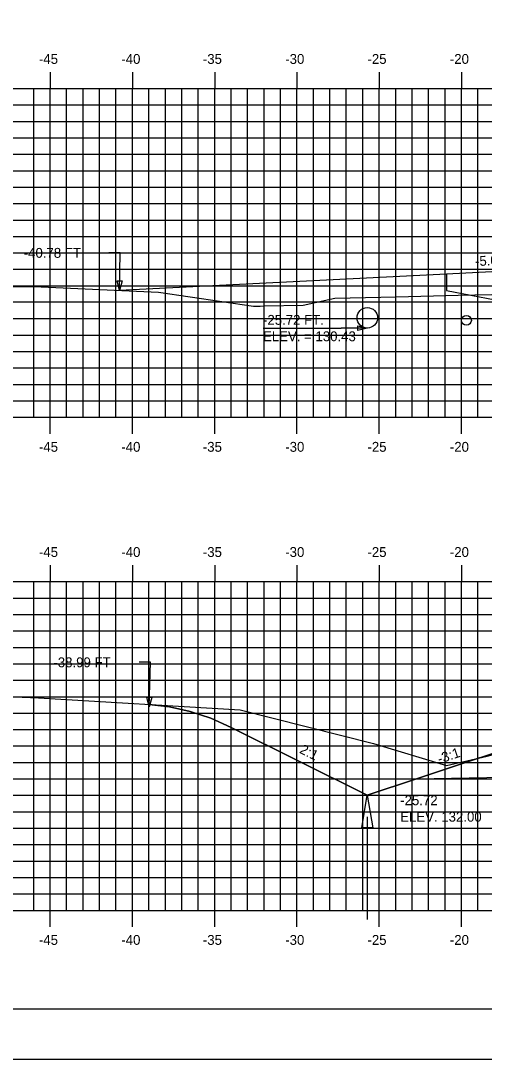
# Model space of a CAD drawing. Extents: x 1145416 to 1145586, y 608981 to 609091.
# Drawn here: x 1145452.1 to 1145480.3, y 608981.3 to 609044.5 of the extents above; entities that cross this region are included whole.
import ezdxf

# ---------------------------------------------------------------- set-up
doc = ezdxf.new("R2010")
doc.units = 0
for name, color, linetype in [('ANNOTATION', 7, 'Continuous'), ('BORDER', 7, 'Continuous'), ('D_Drainage_Culvert', 7, 'Continuous'), ('D_Drainage_Ditch_Line', 7, 'Continuous'), ('D_Roadway_SlopeLines', 7, 'Continuous'), ('D_Roadway_SubGrade', 7, 'Continuous'), ('D_Text_Standard', 7, 'Continuous'), ('H_V ANNOTATION', 7, 'Continuous'), ('MAJOR', 7, 'Continuous'), ('MINOR', 7, 'Continuous'), ('PLOT BOUNDARY', 7, 'Continuous'), ('S_Drainage_Invert', 7, 'Continuous'), ('S_Roadway_Centerline', 7, 'Continuous')]:
    doc.layers.add(name, color=color, linetype=linetype)

msp = doc.modelspace()

# ---------------------------------------------------------------- linework, layer by layer
msp.add_lwpolyline([(1145459.897, 609002.864), (1145461.147, 609002.721), (1145462.397, 609002.44), (1145463.647, 609002.022), (1145464.897, 609001.465), (1145473.164, 608997.332), (1145476.164, 608998.332), (1145483.888, 609000.906), (1145483.889, 609000.906), (1145487.889, 609001.066), (1145498.889, 609001.286), (1145509.889, 609001.066), (1145515.987, 609000.823), (1145523.577, 608998.293), (1145526.577, 608997.293), (1145535.165, 609001.587), (1145536.415, 609002.14), (1145537.665, 609002.548), (1145538.915, 609002.812), (1145540.165, 609002.931)])
at = {"layer": 'BORDER'}
msp.add_lwpolyline([(1145423.889, 608984.335), (1145583.889, 608984.335), (1145583.889, 609089.335), (1145423.889, 609089.335)], close=True, dxfattribs=at)
at = {"layer": 'D_Drainage_Culvert'}
msp.add_circle((1145473.164, 609026.386), 0.625, dxfattribs=at)
at = {"layer": 'D_Drainage_Ditch_Line'}
msp.add_line((1145473.164, 608996.02), (1145473.164, 608989.776), dxfattribs=at)
msp.add_lwpolyline([(1145473.492, 608995.363), (1145472.836, 608995.363), (1145473.164, 608997.332)], close=True, dxfattribs=at)
at = {"layer": 'D_Roadway_SlopeLines'}
msp.add_line((1145477.987, 609029.04), (1145458.109, 609028.05), dxfattribs=at)
for points in [[(1145473.164, 608997.332), (1145464.897, 609001.465), (1145463.647, 609002.022), (1145462.397, 609002.44), (1145461.147, 609002.721), (1145459.897, 609002.864)], [(1145476.164, 608998.332), (1145473.164, 608997.332)]]:
    msp.add_lwpolyline(points, dxfattribs=at)
at = {"layer": 'D_Roadway_SubGrade'}
for points in [[(1145477.987, 609028.04), (1145483.889, 609026.915), (1145487.889, 609026.995), (1145487.889, 609029.079), (1145487.889, 609029.245), (1145483.889, 609029.085), (1145483.889, 609029.335), (1145477.987, 609029.04)], [(1145487.889, 609000.65), (1145487.889, 609000.816), (1145483.889, 609000.656), (1145483.889, 609000.906), (1145483.888, 609000.906), (1145476.164, 608998.332), (1145487.889, 608998.566)]]:
    msp.add_lwpolyline(points, close=True, dxfattribs=at)
at = {"layer": 'D_Text_Standard'}
msp.add_line((1145466.825, 609025.761), (1145471.583, 609025.761), dxfattribs=at)
for points in [[(1145458.109, 609028.05), (1145458.139, 609030.337), (1145457.459, 609030.337)], [(1145473.164, 609025.761), (1145472.263, 609025.761), (1145471.583, 609025.761)], [(1145459.897, 609002.715), (1145459.986, 609005.425), (1145459.306, 609005.425)]]:
    msp.add_lwpolyline(points, dxfattribs=at)
for points in [[(1145458.109, 609028.05), (1145457.971, 609028.634), (1145458.262, 609028.63)], [(1145473.164, 609025.761), (1145472.582, 609025.615), (1145472.582, 609025.906)], [(1145459.897, 609002.715), (1145459.771, 609003.302), (1145460.061, 609003.292)]]:
    msp.add_lwpolyline(points, close=True, dxfattribs=at)
at = {"layer": 'MAJOR'}
for p, q in [((1145453.889, 609041.337), (1145453.889, 609040.335)), ((1145458.889, 609041.337), (1145458.889, 609040.335)), ((1145463.889, 609041.337), (1145463.889, 609040.335)), ((1145468.889, 609041.337), (1145468.889, 609040.335)), ((1145473.889, 609041.337), (1145473.889, 609040.335)), ((1145478.889, 609041.337), (1145478.889, 609040.335)), ((1145428.889, 609040.335), (1145568.889, 609040.335)), ((1145428.889, 609040.335), (1145568.889, 609040.335)), ((1145453.889, 609020.335), (1145453.889, 609040.335)), ((1145458.889, 609020.335), (1145458.889, 609040.335)), ((1145463.889, 609020.335), (1145463.889, 609040.335)), ((1145468.889, 609020.335), (1145468.889, 609040.335)), ((1145473.889, 609020.335), (1145473.889, 609040.335)), ((1145478.889, 609020.335), (1145478.889, 609040.335)), ((1145428.889, 609035.335), (1145568.889, 609035.335)), ((1145428.889, 609030.335), (1145568.889, 609030.335)), ((1145428.889, 609025.335), (1145568.889, 609025.335)), ((1145428.889, 609020.335), (1145568.889, 609020.335)), ((1145428.889, 609020.335), (1145568.889, 609020.335)), ((1145453.889, 609019.333), (1145453.889, 609020.335)), ((1145458.889, 609019.333), (1145458.889, 609020.335)), ((1145463.889, 609019.333), (1145463.889, 609020.335)), ((1145468.889, 609019.333), (1145468.889, 609020.335)), ((1145473.889, 609019.333), (1145473.889, 609020.335)), ((1145478.889, 609019.333), (1145478.889, 609020.335)), ((1145453.889, 609011.337), (1145453.889, 609010.335)), ((1145458.889, 609011.337), (1145458.889, 609010.335)), ((1145463.889, 609011.337), (1145463.889, 609010.335)), ((1145468.889, 609011.337), (1145468.889, 609010.335)), ((1145473.889, 609011.337), (1145473.889, 609010.335)), ((1145478.889, 609011.337), (1145478.889, 609010.335)), ((1145428.889, 609010.335), (1145568.889, 609010.335)), ((1145428.889, 609010.335), (1145568.889, 609010.335)), ((1145453.889, 608990.335), (1145453.889, 609010.335)), ((1145458.889, 608990.335), (1145458.889, 609010.335)), ((1145463.889, 608990.335), (1145463.889, 609010.335)), ((1145468.889, 608990.335), (1145468.889, 609010.335)), ((1145473.889, 608990.335), (1145473.889, 609010.335)), ((1145478.889, 608990.335), (1145478.889, 609010.335)), ((1145428.889, 609005.335), (1145568.889, 609005.335)), ((1145428.889, 609000.335), (1145568.889, 609000.335)), ((1145428.889, 608995.335), (1145568.889, 608995.335)), ((1145428.889, 608990.335), (1145568.889, 608990.335)), ((1145428.889, 608990.335), (1145568.889, 608990.335)), ((1145453.889, 608989.333), (1145453.889, 608990.335)), ((1145458.889, 608989.333), (1145458.889, 608990.335)), ((1145463.889, 608989.333), (1145463.889, 608990.335)), ((1145468.889, 608989.333), (1145468.889, 608990.335)), ((1145473.889, 608989.333), (1145473.889, 608990.335)), ((1145478.889, 608989.333), (1145478.889, 608990.335))]:
    msp.add_line(p, q, dxfattribs=at)
at = {"layer": 'MINOR'}
for p, q in [((1145452.889, 609020.335), (1145452.889, 609040.335)), ((1145454.889, 609020.335), (1145454.889, 609040.335)), ((1145455.889, 609020.335), (1145455.889, 609040.335)), ((1145456.889, 609020.335), (1145456.889, 609040.335)), ((1145457.889, 609020.335), (1145457.889, 609040.335)), ((1145459.889, 609020.335), (1145459.889, 609040.335)), ((1145460.889, 609020.335), (1145460.889, 609040.335)), ((1145461.889, 609020.335), (1145461.889, 609040.335)), ((1145462.889, 609020.335), (1145462.889, 609040.335)), ((1145464.889, 609020.335), (1145464.889, 609040.335)), ((1145465.889, 609020.335), (1145465.889, 609040.335)), ((1145466.889, 609020.335), (1145466.889, 609040.335)), ((1145467.889, 609020.335), (1145467.889, 609040.335)), ((1145469.889, 609020.335), (1145469.889, 609040.335)), ((1145470.889, 609020.335), (1145470.889, 609040.335)), ((1145471.889, 609020.335), (1145471.889, 609040.335)), ((1145472.889, 609020.335), (1145472.889, 609040.335)), ((1145474.889, 609020.335), (1145474.889, 609040.335)), ((1145475.889, 609020.335), (1145475.889, 609040.335)), ((1145476.889, 609020.335), (1145476.889, 609040.335)), ((1145477.889, 609020.335), (1145477.889, 609040.335)), ((1145479.889, 609020.335), (1145479.889, 609040.335)), ((1145428.889, 609039.335), (1145568.889, 609039.335)), ((1145428.889, 609038.335), (1145568.889, 609038.335)), ((1145428.889, 609037.335), (1145568.889, 609037.335)), ((1145428.889, 609036.335), (1145568.889, 609036.335)), ((1145428.889, 609034.335), (1145568.889, 609034.335)), ((1145428.889, 609033.335), (1145568.889, 609033.335)), ((1145428.889, 609032.335), (1145568.889, 609032.335)), ((1145428.889, 609031.335), (1145568.889, 609031.335)), ((1145428.889, 609029.335), (1145568.889, 609029.335)), ((1145428.889, 609028.335), (1145568.889, 609028.335)), ((1145568.889, 609027.335), (1145428.889, 609027.335)), ((1145428.889, 609026.335), (1145568.889, 609026.335)), ((1145428.889, 609024.335), (1145568.889, 609024.335)), ((1145428.889, 609023.335), (1145568.889, 609023.335)), ((1145428.889, 609022.335), (1145568.889, 609022.335)), ((1145428.889, 609021.335), (1145568.889, 609021.335)), ((1145452.889, 608990.335), (1145452.889, 609010.335)), ((1145454.889, 608990.335), (1145454.889, 609010.335)), ((1145455.889, 608990.335), (1145455.889, 609010.335)), ((1145456.889, 608990.335), (1145456.889, 609010.335)), ((1145457.889, 608990.335), (1145457.889, 609010.335)), ((1145459.889, 608990.335), (1145459.889, 609010.335)), ((1145460.889, 608990.335), (1145460.889, 609010.335)), ((1145461.889, 608990.335), (1145461.889, 609010.335)), ((1145462.889, 608990.335), (1145462.889, 609010.335)), ((1145464.889, 608990.335), (1145464.889, 609010.335)), ((1145465.889, 608990.335), (1145465.889, 609010.335)), ((1145466.889, 608990.335), (1145466.889, 609010.335)), ((1145467.889, 608990.335), (1145467.889, 609010.335)), ((1145469.889, 608990.335), (1145469.889, 609010.335)), ((1145470.889, 608990.335), (1145470.889, 609010.335)), ((1145471.889, 608990.335), (1145471.889, 609010.335)), ((1145472.889, 608990.335), (1145472.889, 609010.335)), ((1145474.889, 608990.335), (1145474.889, 609010.335)), ((1145475.889, 608990.335), (1145475.889, 609010.335)), ((1145476.889, 608990.335), (1145476.889, 609010.335)), ((1145477.889, 608990.335), (1145477.889, 609010.335)), ((1145479.889, 608990.335), (1145479.889, 609010.335)), ((1145428.889, 609009.335), (1145568.889, 609009.335)), ((1145428.889, 609008.335), (1145568.889, 609008.335)), ((1145428.889, 609007.335), (1145568.889, 609007.335)), ((1145428.889, 609006.335), (1145568.889, 609006.335)), ((1145428.889, 609004.335), (1145568.889, 609004.335)), ((1145428.889, 609003.335), (1145568.889, 609003.335)), ((1145428.889, 609002.335), (1145568.889, 609002.335)), ((1145428.889, 609001.335), (1145568.889, 609001.335)), ((1145428.889, 608999.335), (1145568.889, 608999.335)), ((1145428.889, 608998.335), (1145568.889, 608998.335)), ((1145428.889, 608997.335), (1145568.889, 608997.335)), ((1145428.889, 608996.335), (1145568.889, 608996.335)), ((1145428.889, 608994.335), (1145568.889, 608994.335)), ((1145428.889, 608993.335), (1145568.889, 608993.335)), ((1145428.889, 608992.335), (1145568.889, 608992.335)), ((1145428.889, 608991.335), (1145568.889, 608991.335))]:
    msp.add_line(p, q, dxfattribs=at)
at = {"layer": 'PLOT BOUNDARY'}
msp.add_lwpolyline([(1145415.795, 608981.276), (1145585.795, 608981.276), (1145585.795, 609091.276), (1145415.795, 609091.276)], close=True, dxfattribs=at)
at = {"layer": 'S_Drainage_Invert'}
msp.add_circle((1145479.188, 609026.231), 0.3, dxfattribs=at)
at = {"layer": 'S_Roadway_Centerline'}
for points in [[(1145438.43, 609028.386), (1145453.335, 609028.272), (1145460.467, 609027.94), (1145466.247, 609027.089), (1145466.648, 609027.096), (1145466.887, 609027.122), (1145469.265, 609027.152), (1145471.189, 609027.579), (1145474.917, 609027.67), (1145478.695, 609027.772), (1145481.741, 609027.82), (1145482.031, 609027.818), (1145485.039, 609028.121), (1145486.704, 609028.157), (1145496.051, 609028.259), (1145505.332, 609028.136), (1145507.282, 609028.095), (1145510.304, 609027.832), (1145510.979, 609027.773), (1145513.518, 609027.042), (1145513.931, 609026.847), (1145518.014, 609028.583), (1145525.127, 609031.11)], [(1145440.356, 609003.793), (1145453.175, 609003.264), (1145465.44, 609002.534), (1145473.538, 609000.489), (1145477.984, 608999.152), (1145480.44, 608999.716), (1145482.168, 609000.197), (1145484.192, 609000.33), (1145484.829, 609000.367), (1145486.595, 609000.386), (1145495.634, 609000.566), (1145497.444, 609000.542), (1145506.677, 609000.41), (1145507.295, 609000.357), (1145510.974, 609000.051), (1145513.492, 608999.566), (1145513.977, 608999.427), (1145517.137, 609000.366), (1145523.601, 609002.296), (1145524.098, 609002.327), (1145545.847, 609003.145)]]:
    msp.add_lwpolyline(points, dxfattribs=at)

# ---------------------------------------------------------------- texts
at = {"layer": 'ANNOTATION'}
for s, rotation, p in [('-5.0%', 2.86241, (1145479.723, 609029.528)), ('2:1', 333.43495, (1145468.997, 608999.933)), ('-3:1', 18.43482, (1145477.543, 608999.246))]:
    msp.add_text(s, height=0.6, rotation=rotation, dxfattribs=at).set_placement(p)
at = {"layer": 'D_Text_Standard'}
for s, p in [('-40.78 FT', (1145452.282, 609030.037)), ('-25.72 FT.', (1145466.825, 609025.961)), ('ELEV. = 130.43', (1145466.825, 609024.961)), ('-38.99 FT', (1145454.087, 609005.125)), ('-25.72', (1145475.164, 608996.732)), ('ELEV. 132.00', (1145475.164, 608995.73))]:
    msp.add_text(s, height=0.6, dxfattribs=at).set_placement(p)
at = {"layer": 'H_V ANNOTATION'}
for s, p in [('-45', (1145453.206, 609041.835)), ('-40', (1145458.214, 609041.835)), ('-35', (1145463.169, 609041.835)), ('-30', (1145468.177, 609041.835)), ('-25', (1145473.174, 609041.835)), ('-20', (1145478.182, 609041.835)), ('-45', (1145453.206, 609018.235)), ('-40', (1145458.214, 609018.235)), ('-35', (1145463.169, 609018.235)), ('-30', (1145468.177, 609018.235)), ('-25', (1145473.174, 609018.235)), ('-20', (1145478.182, 609018.235)), ('-45', (1145453.206, 609011.835)), ('-40', (1145458.214, 609011.835)), ('-35', (1145463.169, 609011.835)), ('-30', (1145468.177, 609011.835)), ('-25', (1145473.174, 609011.835)), ('-20', (1145478.182, 609011.835)), ('-45', (1145453.206, 608988.235)), ('-40', (1145458.214, 608988.235)), ('-35', (1145463.169, 608988.235)), ('-30', (1145468.177, 608988.235)), ('-25', (1145473.174, 608988.235)), ('-20', (1145478.182, 608988.235))]:
    msp.add_text(s, height=0.6, dxfattribs=at).set_placement(p)

doc.saveas('drawing.dxf')
